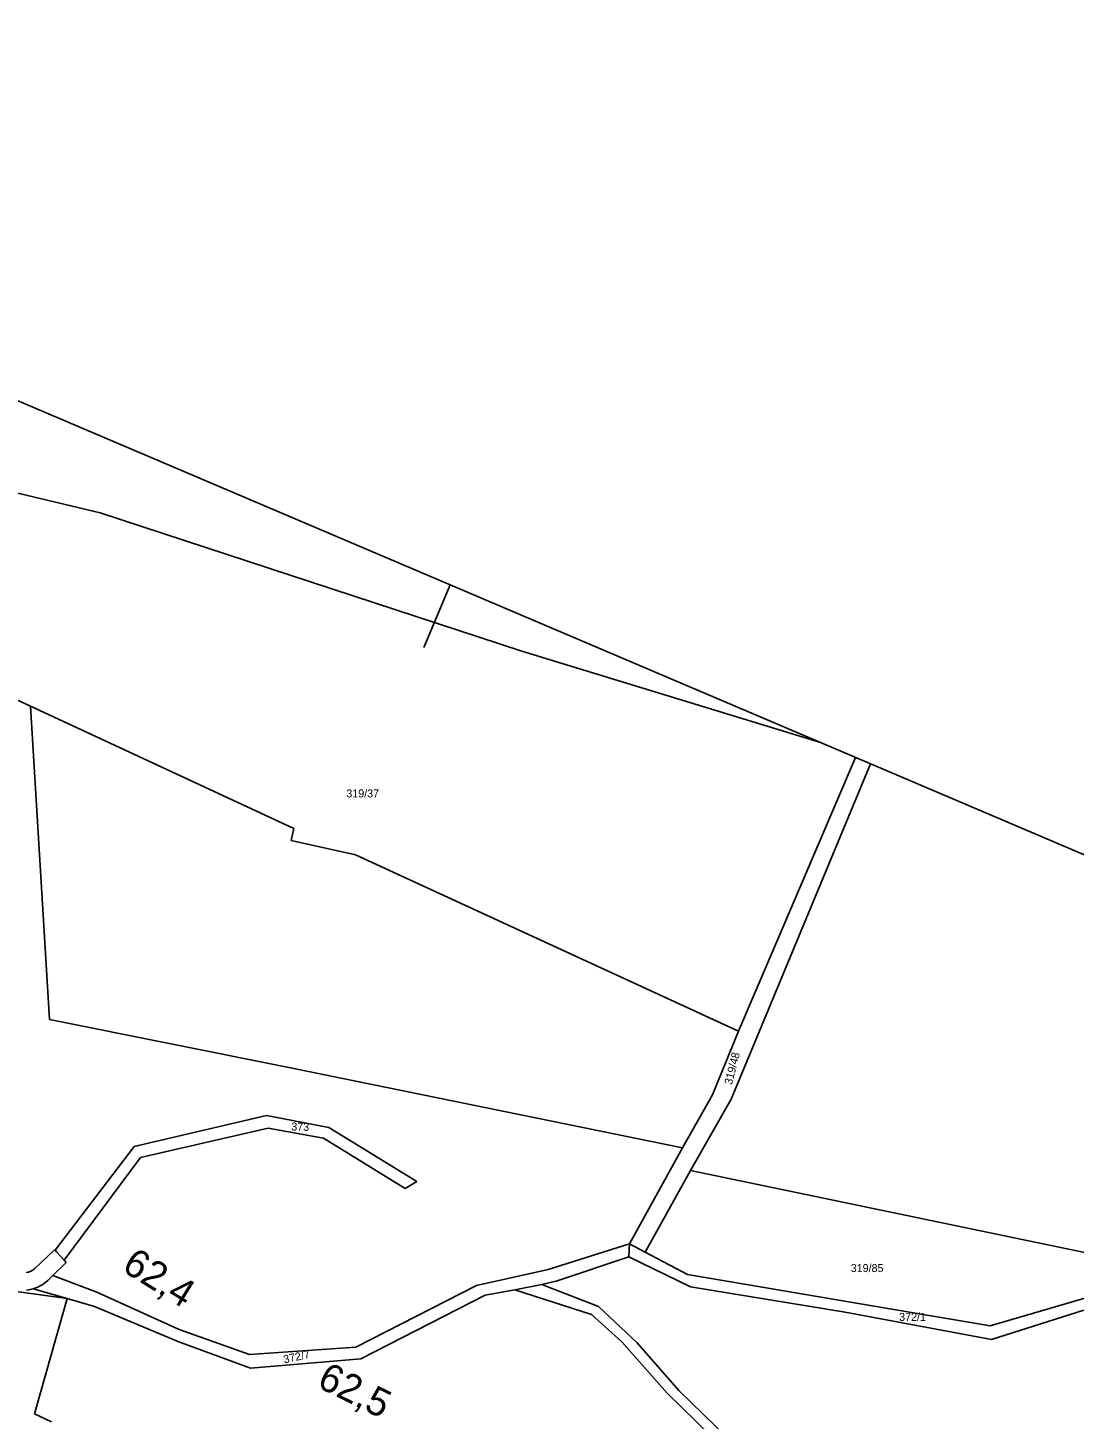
# Model space of a CAD drawing. Extents: x -805826 to -803822, y -1165880 to -1164382.
# Drawn here: x -805114 to -804669, y -1164973 to -1164382 of the extents above; entities that cross this region are included whole.
import ezdxf

# ---------------------------------------------------------------- set-up
doc = ezdxf.new("R2010")
doc.units = 0
for name, color, linetype in [('formát', 7, 'Continuous'), ('kilometráž - 2880', 7, 'Continuous'), ('kn_celek - Cisla pozemkovych parcel', 7, 'Continuous'), ('kn_celek - Hranice parcel', 7, 'Continuous'), ('kn_celek - Vnitrni kresby', 7, 'Continuous')]:
    doc.layers.add(name, color=color, linetype=linetype)

msp = doc.modelspace()

# ---------------------------------------------------------------- linework, layer by layer
at = {"layer": 'formát'}
for p, q in [((-804934.65, -1164618.86), (-805491.17, -1164382.07)), ((-804934.65, -1164618.86), (-804945.93, -1164645.36)), ((-804378.13, -1164855.64), (-804934.65, -1164618.86))]:
    msp.add_line(p, q, dxfattribs=at)
at = {"layer": 'kn_celek - Hranice parcel'}
for p, q in [((-805083.45, -1164588.22), (-805277.24, -1164541.8)), ((-804904.3, -1164646.94), (-805083.45, -1164588.22)), ((-805281.83, -1164592.37), (-805113.11, -1164670.31)), ((-804777.73, -1164685.62), (-804904.3, -1164646.94)), ((-805113.11, -1164670.31), (-805104.96, -1164803.58)), ((-804812.2, -1164808.43), (-804762.41, -1164692.14)), ((-804756.04, -1164694.85), (-804815.34, -1164837.31)), ((-805104.96, -1164803.58), (-805002.5, -1164824.06)), ((-804823.26, -1164835.57), (-804812.2, -1164808.43)), ((-805002.5, -1164824.06), (-804835.9, -1164858.05)), ((-804835.9, -1164858.05), (-804823.26, -1164835.57)), ((-804815.34, -1164837.31), (-804832.6, -1164867.72)), ((-805012.79, -1164844.28), (-805069.02, -1164857.55)), ((-804986.25, -1164849.35), (-805012.79, -1164844.28)), ((-805066.25, -1164862.14), (-805012.1, -1164849.67)), ((-805012.1, -1164849.67), (-804988.57, -1164853.91)), ((-804988.57, -1164853.91), (-804953.82, -1164875.39)), ((-804948.88, -1164872.34), (-804986.25, -1164849.35)), ((-805102.64, -1164901.58), (-805069.02, -1164857.55)), ((-804858.53, -1164898.82), (-804835.9, -1164858.05)), ((-805098.77, -1164905.82), (-805066.25, -1164862.14)), ((-804832.6, -1164867.72), (-804851.87, -1164902.35)), ((-804832.6, -1164867.72), (-804638.79, -1164908.07)), ((-804953.82, -1164875.39), (-804948.88, -1164872.34)), ((-805102.85, -1164901.36), (-805111.32, -1164909.48)), ((-805102.64, -1164901.58), (-805102.85, -1164901.36)), ((-805102.02, -1164902.2), (-805102.64, -1164901.58)), ((-804893.02, -1164909.83), (-804858.53, -1164898.82)), ((-804858.53, -1164898.82), (-804858.83, -1164904.44)), ((-804851.87, -1164902.35), (-804858.53, -1164898.82)), ((-805103.61, -1164912.32), (-805097.9, -1164906.79)), ((-805098.77, -1164905.82), (-805102.02, -1164902.2)), ((-805097.9, -1164906.79), (-805098.77, -1164905.82)), ((-804858.83, -1164904.44), (-804889.29, -1164914.56)), ((-804832.5, -1164917.19), (-804858.83, -1164904.44)), ((-804833.82, -1164911.92), (-804851.87, -1164902.35)), ((-805113.94, -1164910.87), (-805114.91, -1164911.08)), ((-805113, -1164910.53), (-805113.94, -1164910.87)), ((-805112.37, -1164910.19), (-805113, -1164910.53)), ((-805112.14, -1164910.06), (-805112.37, -1164910.19)), ((-805111.32, -1164909.48), (-805112.14, -1164910.06)), ((-805105.77, -1164914.39), (-805103.61, -1164912.32)), ((-805103.61, -1164912.32), (-805084.92, -1164919.43)), ((-804923.48, -1164916.52), (-804893.02, -1164909.83)), ((-804705.25, -1164933.71), (-804833.82, -1164911.92)), ((-805119.1, -1164919.05), (-805097.48, -1164922.09)), ((-805114.78, -1164918.51), (-805113.77, -1164918.39)), ((-805113.77, -1164918.39), (-805111.92, -1164917.96)), ((-805111.92, -1164917.96), (-805109.92, -1164917.26)), ((-805097.48, -1164922.09), (-805111.92, -1164917.96)), ((-805109.92, -1164917.26), (-805109.01, -1164916.78)), ((-805109.01, -1164916.78), (-805108.15, -1164916.27)), ((-805108.15, -1164916.27), (-805107.31, -1164915.69)), ((-805107.31, -1164915.69), (-805105.77, -1164914.39)), ((-805084.92, -1164919.43), (-805049.9, -1164935.2)), ((-804974.79, -1164942.71), (-804923.48, -1164916.52)), ((-804907.23, -1164918.36), (-804919.77, -1164920.68)), ((-804895.81, -1164916.14), (-804907.23, -1164918.36)), ((-804874.58, -1164928.85), (-804907.23, -1164918.36)), ((-804889.29, -1164914.56), (-804895.81, -1164916.14)), ((-804895.81, -1164916.14), (-804871.64, -1164925.44)), ((-804766.79, -1164927.94), (-804832.5, -1164917.19)), ((-805111.37, -1164971.04), (-805097.48, -1164922.09)), ((-805085.83, -1164925.5), (-805097.48, -1164922.09)), ((-804919.77, -1164920.68), (-804972.67, -1164947.71)), ((-804871.64, -1164925.44), (-804855.28, -1164940.89)), ((-804664.89, -1164921.99), (-804705.25, -1164933.71)), ((-805050.08, -1164940.56), (-805085.83, -1164925.5)), ((-804861.79, -1164940.55), (-804874.58, -1164928.85)), ((-804704.68, -1164939.45), (-804766.79, -1164927.94)), ((-804665.39, -1164926.98), (-804704.68, -1164939.45)), ((-805049.9, -1164935.2), (-805020, -1164945.92)), ((-805019.63, -1164951.66), (-805050.08, -1164940.56)), ((-805020, -1164945.92), (-804974.79, -1164942.71)), ((-804842.42, -1164962.28), (-804861.79, -1164940.55)), ((-804855.28, -1164940.89), (-804837.56, -1164961.21)), ((-804972.67, -1164947.71), (-805019.63, -1164951.66)), ((-804781.99, -1165021.41), (-804842.42, -1164962.28)), ((-804837.56, -1164961.21), (-804778.25, -1165018.66)), ((-805104.08, -1164974.52), (-805111.37, -1164971.04))]:
    msp.add_line(p, q, dxfattribs=at)
at = {"layer": 'kn_celek - Vnitrni kresby'}
for p, q in [((-805113.11, -1164670.31), (-805001.16, -1164722.3)), ((-805001.16, -1164722.3), (-805002.28, -1164727.42)), ((-805002.28, -1164727.42), (-804975.01, -1164733.47)), ((-804975.01, -1164733.47), (-804812.2, -1164808.43))]:
    msp.add_line(p, q, dxfattribs=at)

# ---------------------------------------------------------------- texts
at = {"layer": 'kilometráž - 2880'}
for s, rotation, p in [('62,4', 328.34768, (-805074.72, -1164910.09)), ('62,5', 333.66392, (-804991.8, -1164959.45))]:
    msp.add_text(s, height=12, rotation=rotation, dxfattribs=at).set_placement(p)
at = {"layer": 'kn_celek - Cisla pozemkovych parcel'}
for s, p in [('319/37', (-804978.83, -1164709.14)), ('319/85', (-804764.45, -1164910.86)), ('372/1', (-804743.88, -1164931.61))]:
    msp.add_text(s, height=3.4, dxfattribs=at).set_placement(p)
for s, rotation, p in [('319/48', 75.69, (-804814.96, -1164831.45)), ('373', 358.497, (-805002.26, -1164850.68)), ('372/7', 12.087, (-805005.19, -1164949.68))]:
    msp.add_text(s, height=3.4, rotation=rotation, dxfattribs=at).set_placement(p)

doc.saveas('drawing.dxf')
